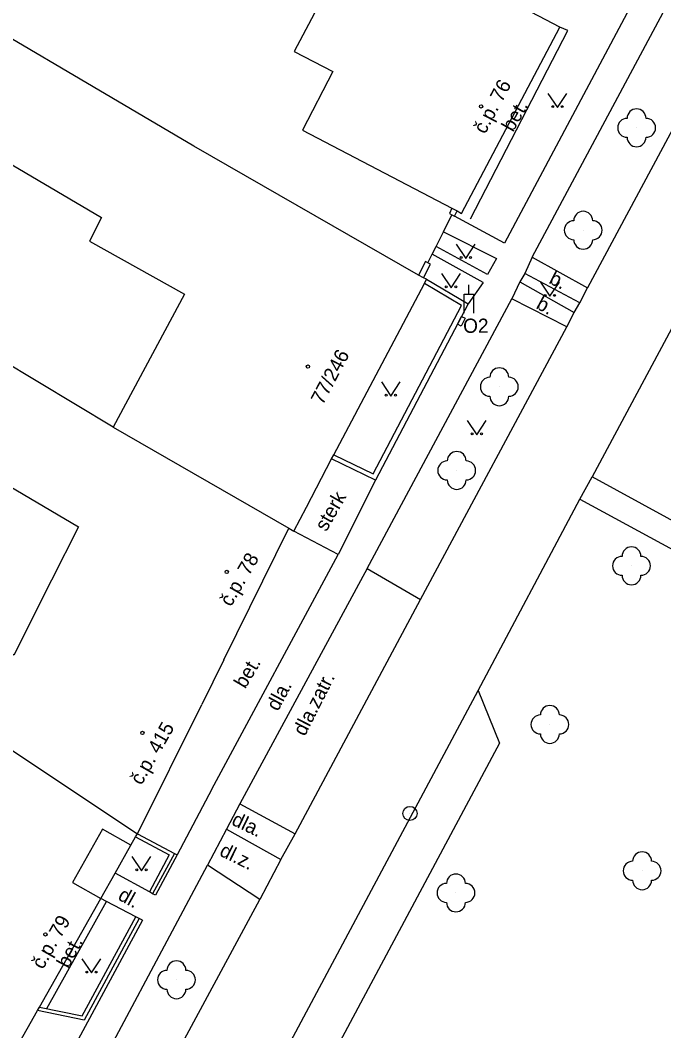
# Model space of a CAD drawing. Extents: x -577457 to -568404, y -1208466 to -1201387.
# Drawn here: x -568797.6 to -568763.6, y -1203865.9 to -1203812.5 of the extents above; entities that cross this region are included whole.
import ezdxf

# ---------------------------------------------------------------- set-up
doc = ezdxf.new("R2010")
doc.units = 0
for name, color, linetype in [('BUDOVY_MĚŘ', 7, 'Continuous'), ('BUDOVY_NEMĚŘ', 7, 'Continuous'), ('MAP_ZN_BP', 7, 'Continuous'), ('OBVOD_PILÍŘE', 7, 'Continuous'), ('POMOC_POPIS', 7, 'Continuous'), ('ROZHRANÍ_PLOCH', 7, 'Continuous'), ('ZELEŇ', 7, 'Continuous'), ('ZN_BUDOV', 7, 'Continuous'), ('ZN_DOPLŇKOVÉ', 7, 'Continuous'), ('ZN_KULTUR', 7, 'Continuous'), ('Č_POPIS_ORIENT', 7, 'Continuous')]:
    doc.layers.add(name, color=color, linetype=linetype)

msp = doc.modelspace()

# ---------------------------------------------------------------- linework, layer by layer
at = {"layer": 'BUDOVY_MĚŘ'}
for points in [[(-568774.3, -1203822.67), (-568769.12, -1203812.83), (-568771.37, -1203811.65)], [(-568774.81, -1203822.4), (-568774.54, -1203822.54)], [(-568774.54, -1203822.54), (-568774.3, -1203822.67)], [(-568781.05, -1203835.42), (-568776.26, -1203826.37)], [(-568776.31, -1203826.07), (-568776.57, -1203825.93)], [(-568776.15, -1203826.15), (-568776.31, -1203826.07)], [(-568776.26, -1203826.37), (-568776.15, -1203826.15)], [(-568781.17, -1203835.64), (-568781.05, -1203835.42)], [(-568783.16, -1203839.45), (-568782.5, -1203838.19)], [(-568786.86, -1203846.26), (-568783.43, -1203839.3)], [(-568783.43, -1203839.3), (-568783.16, -1203839.45)], [(-568791.42, -1203855.44), (-568788.02, -1203848.61)], [(-568791.77, -1203856.05), (-568793.27, -1203855.2), (-568794.85, -1203858.02), (-568793.36, -1203858.86)], [(-568791.77, -1203856.05), (-568791.52, -1203855.61)], [(-568791.52, -1203855.61), (-568791.42, -1203855.44)], [(-568792.6, -1203857.52), (-568791.77, -1203856.05)], [(-568793.36, -1203858.86), (-568792.6, -1203857.52)], [(-568796.59, -1203864.6), (-568793.36, -1203858.86)], [(-568798.17, -1203867.41), (-568796.69, -1203864.78)], [(-568796.69, -1203864.78), (-568796.59, -1203864.6)]]:
    msp.add_lwpolyline(points, dxfattribs=at)
at = {"layer": 'BUDOVY_NEMĚŘ'}
for points in [[(-568771.37, -1203811.65), (-568785.39, -1203804.05), (-568786.46, -1203806.15), (-568780.55, -1203809.22), (-568783.15, -1203814.11), (-568781.11, -1203815.18), (-568782.71, -1203818.27), (-568774.81, -1203822.4)], [(-568776.57, -1203825.93), (-568788.44, -1203819.12), (-568804.1, -1203809.88), (-568806.44, -1203808.59), (-568808.85, -1203812.83), (-568807.34, -1203813.6), (-568807.79, -1203814.36), (-568793.31, -1203822.89), (-568793.96, -1203824.14), (-568788.93, -1203826.94), (-568792.7, -1203833.97), (-568783.43, -1203839.3)], [(-568792.7, -1203833.97), (-568800.67, -1203829.18), (-568802.98, -1203833.39), (-568801.09, -1203834.5), (-568801.47, -1203835.15), (-568794.54, -1203839.23), (-568795.96, -1203842.05), (-568797.94, -1203846.01), (-568809.76, -1203837.98), (-568812.22, -1203841.59), (-568791.42, -1203855.44)]]:
    msp.add_lwpolyline(points, dxfattribs=at)
at = {"layer": 'MAP_ZN_BP'}
for radius in [0.375, 0.0005]:
    msp.add_circle((-568777.03, -1203854.371), radius, dxfattribs=at)
at = {"layer": 'OBVOD_PILÍŘE'}
msp.add_lwpolyline([(-568774.22, -1203828.42), (-568774.33, -1203828.63), (-568774.52, -1203828.53), (-568774.31, -1203828.11), (-568774.11, -1203828.21), (-568774.22, -1203828.42)], dxfattribs=at)
at = {"layer": 'ROZHRANÍ_PLOCH'}
for points in [[(-568750, -1203793.65), (-568756.6, -1203805.98), (-568767.65, -1203826.6)], [(-568770.57, -1203824.98), (-568755.27, -1203796.38)], [(-568758.82, -1203799.39), (-568772.04, -1203824.25)], [(-568773.83, -1203822.95), (-568768.69, -1203813.01)], [(-568768.69, -1203813.01), (-568769.12, -1203812.83)], [(-568757.98, -1203818.98), (-568767.4, -1203836.58)], [(-568772.04, -1203824.25), (-568774.67, -1203822.81)], [(-568775.26, -1203823.64), (-568772.46, -1203825.05)], [(-568772.93, -1203825.9), (-568775.65, -1203824.42)], [(-568773.16, -1203826.32), (-568775.85, -1203824.82)], [(-568772.46, -1203825.05), (-568772.93, -1203825.9)], [(-568770.57, -1203824.98), (-568770.97, -1203825.84)], [(-568770.57, -1203824.98), (-568767.65, -1203826.6)], [(-568770.97, -1203825.84), (-568771.22, -1203826.28)], [(-568768.06, -1203827.39), (-568770.97, -1203825.84)], [(-568773.16, -1203826.32), (-568773.96, -1203827.45)], [(-568771.22, -1203826.28), (-568771.65, -1203827.19)], [(-568771.22, -1203826.28), (-568768.35, -1203827.91)], [(-568768.06, -1203827.39), (-568767.65, -1203826.6)], [(-568779.29, -1203841.43), (-568771.65, -1203827.19)], [(-568768.75, -1203828.67), (-568771.65, -1203827.19)], [(-568768.35, -1203827.91), (-568768.06, -1203827.39)], [(-568768.75, -1203828.67), (-568768.35, -1203827.91)], [(-568776.47, -1203843.07), (-568768.75, -1203828.67)], [(-568778.85, -1203836.77), (-568780.82, -1203840.69), (-568783.16, -1203839.45)], [(-568768.05, -1203837.76), (-568767.4, -1203836.58)], [(-568755.71, -1203842.98), (-568767.4, -1203836.58)], [(-568773.42, -1203847.87), (-568768.05, -1203837.76)], [(-568768.05, -1203837.76), (-568756.35, -1203844.13)], [(-568787.5, -1203853.09), (-568780.82, -1203840.69)], [(-568779.29, -1203841.43), (-568786.01, -1203853.86)], [(-568779.29, -1203841.43), (-568776.47, -1203843.07)], [(-568783.09, -1203855.45), (-568776.47, -1203843.07)], [(-568801.63, -1203900.65), (-568773.42, -1203847.87)], [(-568773.42, -1203847.87), (-568772.3, -1203850.66)], [(-568772.3, -1203850.66), (-568794.61, -1203892.39)], [(-568787.5, -1203853.09), (-568789.32, -1203856.55)], [(-568786.01, -1203853.86), (-568786.72, -1203855.21)], [(-568786.01, -1203853.86), (-568783.09, -1203855.45)], [(-568786.72, -1203855.21), (-568787.72, -1203857.1)], [(-568786.72, -1203855.21), (-568783.85, -1203856.8)], [(-568783.85, -1203856.8), (-568783.09, -1203855.45)], [(-568789.46, -1203856.48), (-568789.32, -1203856.55), (-568790.47, -1203858.69)], [(-568783.85, -1203856.8), (-568784.96, -1203858.92)], [(-568794.81, -1203870.42), (-568787.72, -1203857.1)], [(-568784.96, -1203858.92), (-568787.72, -1203857.1)], [(-568790.79, -1203858.51), (-568792.6, -1203857.52)], [(-568796.25, -1203879.87), (-568784.96, -1203858.92)], [(-568793.05, -1203859.02), (-568793.36, -1203858.86)], [(-568790.62, -1203858.61), (-568790.79, -1203858.51)], [(-568790.47, -1203858.69), (-568790.62, -1203858.61)], [(-568796.21, -1203864.68), (-568793.05, -1203859.02)], [(-568791.5, -1203859.83), (-568793.05, -1203859.02)], [(-568791.16, -1203860.01), (-568795.76, -1203868.57)], [(-568791.33, -1203859.92), (-568791.5, -1203859.83)], [(-568791.16, -1203860.01), (-568791.33, -1203859.92)]]:
    msp.add_lwpolyline(points, dxfattribs=at)
at = {"layer": 'ZELEŇ'}
for centre in [(-568765.06, -1203818.15), (-568767.88, -1203823.56), (-568772.31, -1203831.83), (-568774.56, -1203836.25), (-568765.33, -1203841.29), (-568769.64, -1203849.67), (-568764.77, -1203857.4), (-568774.6, -1203858.57), (-568789.36, -1203863.16)]:
    msp.add_circle(centre, 0.0005, dxfattribs=at)
for centre, start, end in [((-568765.06, -1203817.65), 0, 180), ((-568765.56, -1203818.15), 90, 270), ((-568764.56, -1203818.15), 270, 90), ((-568765.06, -1203818.65), 180, 360), ((-568767.88, -1203823.06), 0, 180), ((-568768.38, -1203823.56), 90, 270), ((-568767.38, -1203823.56), 270, 90), ((-568767.88, -1203824.06), 180, 360), ((-568772.31, -1203831.33), 0, 180), ((-568772.81, -1203831.83), 90, 270), ((-568771.81, -1203831.83), 270, 90), ((-568772.31, -1203832.33), 180, 360), ((-568774.56, -1203835.75), 0, 180), ((-568775.06, -1203836.25), 90, 270), ((-568774.06, -1203836.25), 270, 90), ((-568774.56, -1203836.75), 180, 360), ((-568765.83, -1203841.29), 90, 270), ((-568765.33, -1203840.79), 0, 180), ((-568764.83, -1203841.29), 270, 90), ((-568765.33, -1203841.79), 180, 360), ((-568769.64, -1203849.17), 0, 180), ((-568770.14, -1203849.67), 90, 270), ((-568769.14, -1203849.67), 270, 90), ((-568769.64, -1203850.17), 180, 360), ((-568764.77, -1203856.9), 0, 180), ((-568765.27, -1203857.4), 90, 270), ((-568764.27, -1203857.4), 270, 90), ((-568774.6, -1203858.07), 0, 180), ((-568775.1, -1203858.57), 90, 270), ((-568774.1, -1203858.57), 270, 90), ((-568764.77, -1203857.9), 180, 360), ((-568774.6, -1203859.07), 180, 360), ((-568789.86, -1203863.16), 90, 270), ((-568789.36, -1203862.66), 0, 180), ((-568788.86, -1203863.16), 270, 90), ((-568789.36, -1203863.66), 180, 360)]:
    msp.add_arc(centre, 0.5, start, end, dxfattribs=at)
at = {"layer": 'ZN_BUDOV'}
for centre in [(-568773.27, -1203817.02), (-568782.42, -1203830.76), (-568786.7, -1203841.61), (-568791.16, -1203850.12), (-568796.28, -1203860.76)]:
    msp.add_circle(centre, 0.0875, dxfattribs=at)
at = {"layer": 'ZN_DOPLŇKOVÉ'}
msp.add_line((-568773.92, -1203826.94), (-568773.92, -1203826.44), dxfattribs=at)
for points in [[(-568774.81, -1203822.4), (-568774.94, -1203822.68), (-568774.81, -1203822.74)], [(-568774.81, -1203822.74), (-568774.67, -1203822.81), (-568774.54, -1203822.54)], [(-568775.85, -1203824.82), (-568775.65, -1203824.42), (-568775.26, -1203823.64), (-568774.81, -1203822.74)], [(-568776.08, -1203825.28), (-568776.21, -1203825.21), (-568776.57, -1203825.93)], [(-568776.31, -1203826.07), (-568775.94, -1203825.35), (-568776.08, -1203825.28)], [(-568776.08, -1203825.28), (-568775.85, -1203824.82)], [(-568781.05, -1203835.42), (-568778.97, -1203836.43), (-568774.31, -1203827.53), (-568776.26, -1203826.37)], [(-568776.15, -1203826.15), (-568773.96, -1203827.45)], [(-568774.17, -1203827.94), (-568774.17, -1203826.94), (-568773.67, -1203826.94), (-568773.67, -1203827.94)], [(-568773.96, -1203827.45), (-568778.85, -1203836.77)], [(-568782.5, -1203838.19), (-568781.17, -1203835.64)], [(-568778.85, -1203836.77), (-568781.17, -1203835.64)], [(-568786.86, -1203846.26), (-568788.02, -1203848.61)], [(-568791.52, -1203855.61), (-568789.74, -1203856.56), (-568790.79, -1203858.51)], [(-568791.42, -1203855.44), (-568789.46, -1203856.48)], [(-568789.46, -1203856.48), (-568790.62, -1203858.61)], [(-568791.33, -1203859.92), (-568794.23, -1203865.29), (-568796.69, -1203864.78)], [(-568796.59, -1203864.6), (-568794.33, -1203865.07), (-568791.5, -1203859.83)]]:
    msp.add_lwpolyline(points, dxfattribs=at)
at = {"layer": 'ZN_KULTUR'}
for points in [[(-568769.74, -1203816.33), (-568769.24, -1203817.08), (-568768.74, -1203816.33)], [(-568774.58, -1203824.3), (-568774.08, -1203825.05), (-568773.58, -1203824.3)], [(-568775.36, -1203825.85), (-568774.86, -1203826.6), (-568774.36, -1203825.85)], [(-568770.14, -1203826.3), (-568769.64, -1203827.05), (-568769.14, -1203826.3)], [(-568778.54, -1203831.57), (-568778.04, -1203832.32), (-568777.54, -1203831.57)], [(-568774, -1203833.62), (-568773.5, -1203834.37), (-568773, -1203833.62)], [(-568791.71, -1203856.65), (-568791.21, -1203857.4), (-568790.71, -1203856.65)], [(-568794.35, -1203862.05), (-568793.85, -1203862.8), (-568793.35, -1203862.05)]]:
    msp.add_lwpolyline(points, dxfattribs=at)
for centre in [(-568769.49, -1203817.03), (-568768.99, -1203817.03), (-568774.33, -1203825), (-568773.83, -1203825), (-568775.11, -1203826.55), (-568774.61, -1203826.55), (-568769.89, -1203827), (-568769.39, -1203827), (-568778.29, -1203832.27), (-568777.79, -1203832.27), (-568773.75, -1203834.32), (-568773.25, -1203834.32), (-568791.46, -1203857.35), (-568790.96, -1203857.35), (-568794.1, -1203862.75), (-568793.6, -1203862.75)]:
    msp.add_circle(centre, 0.05, dxfattribs=at)

# ---------------------------------------------------------------- texts
at = {"layer": 'POMOC_POPIS'}
for s, rotation, p in [('bet.', 60.35, (-568771.59, -1203818.41)), ('b.', 332.73, (-568769.74, -1203826.33)), ('b.', 331.62, (-568770.42, -1203827.66)), ('sterk', 60.13, (-568781.45, -1203839.52)), ('bet.', 59.17, (-568785.73, -1203847.82)), ('dla.zatr.', 63.1, (-568782.58, -1203850.33)), ('dla.', 61.86, (-568784, -1203849.01)), ('dla.', 334.3, (-568786.5, -1203854.94)), ('dl.z.', 333.72, (-568787.14, -1203856.57)), ('dl.', 330.83, (-568792.5, -1203858.89)), ('bet.', 61.88, (-568795.07, -1203862.6))]:
    msp.add_text(s, height=0.75, rotation=rotation, dxfattribs=at).set_placement(p)
msp.add_text('O2', height=0.75, dxfattribs=at).set_placement((-568774.22, -1203828.98))
at = {"layer": 'Č_POPIS_ORIENT'}
for s, rotation, p in [('č.p. 76', 62.25, (-568773.06, -1203818.52)), ('77/246', 62.07, (-568781.64, -1203832.83)), ('č.p. 78', 60, (-568786.48, -1203843.49)), ('č.p. 415', 60.34, (-568791.21, -1203852.92)), ('č.p. 79', 60.58, (-568796.41, -1203862.65))]:
    msp.add_text(s, height=0.75, rotation=rotation, dxfattribs=at).set_placement(p)

doc.saveas('drawing.dxf')
